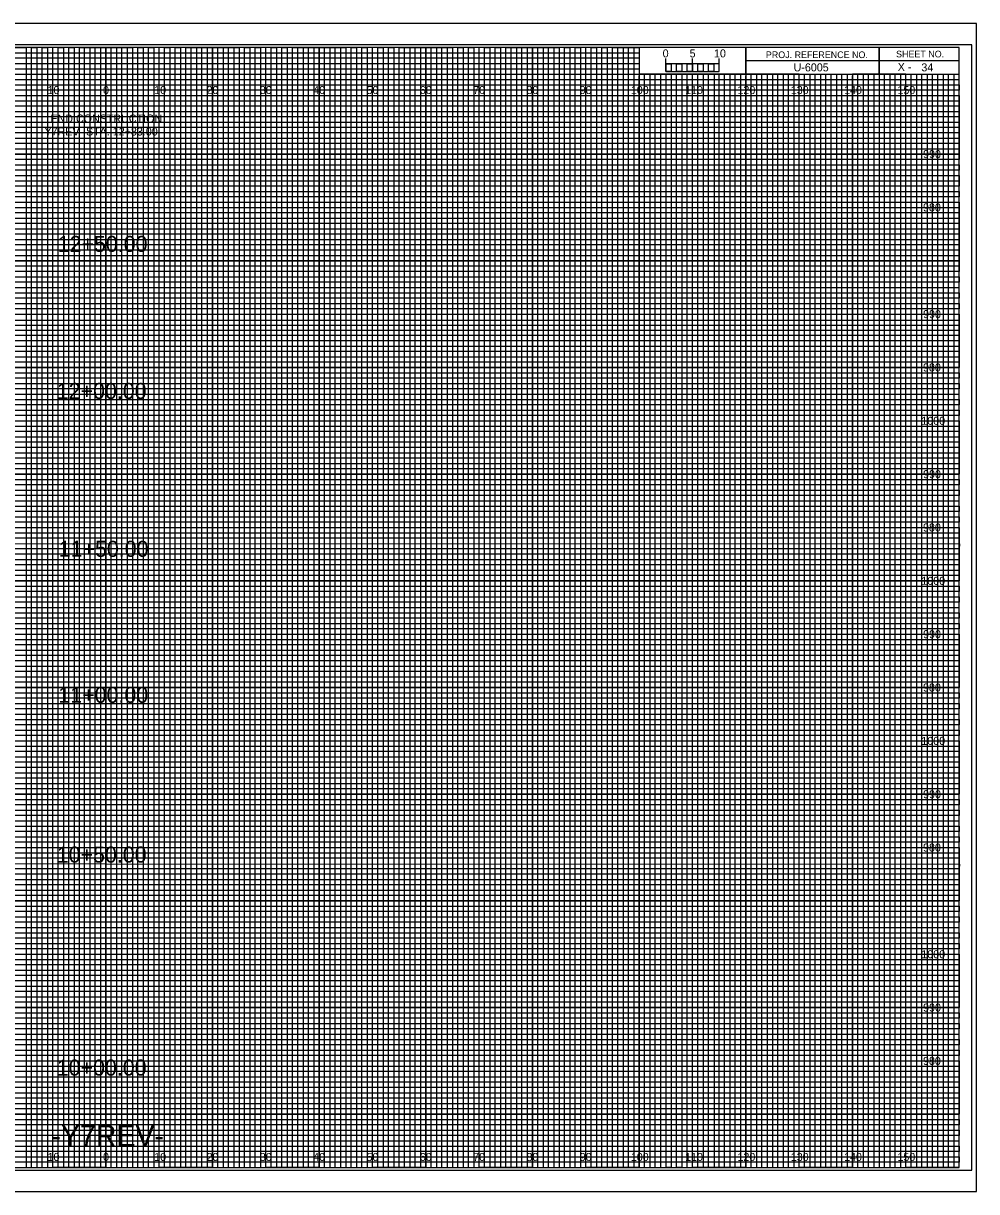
# Model space of a CAD drawing. Extents: x -13 to 323, y -5 to 215.
# Drawn here: x 144.5 to 323.3, y -4.5 to 214.5 of the extents above; entities that cross this region are included whole.
import ezdxf

# ---------------------------------------------------------------- set-up
doc = ezdxf.new("R2010")
doc.units = 0
for name, color, linetype in [('Prop XS Alignment Label', 7, 'Continuous'), ('Prop XS Bar Scale Labels', 7, 'Continuous'), ('Prop XS Elevation Labels', 7, 'Continuous'), ('Prop XS Label Text', 7, 'Continuous'), ('Prop XS Offset Labels', 7, 'Continuous'), ('Prop XS Project Number', 7, 'Continuous'), ('Prop XS Sheet Number', 7, 'Continuous'), ('Prop XS Station Labels', 7, 'Continuous'), ('Sheet Cross Section CELL', 7, 'Continuous'), ('Sheet Cross Section Grid Major CELL', 7, 'Continuous'), ('Sheet Cross Section Grid Middle CELL', 7, 'Continuous'), ('Sheet Cross Section Grid Minor 1 CELL', 7, 'Continuous'), ('Sheet Cross Section Grid Minor 2 CELL', 7, 'Continuous'), ('Sheet Cross Section Scale CELL', 7, 'Continuous'), ('Sheet Cutting Line CELL', 7, 'Continuous'), ('Sheet DOT Grid CELL', 7, 'Continuous'), ('Sheet Plot Border Inside CELL', 7, 'Continuous'), ('Sheet Plot Border Outside CELL', 7, 'Continuous')]:
    doc.layers.add(name, color=color, linetype=linetype)

msp = doc.modelspace()

# ---------------------------------------------------------------- linework, layer by layer
at = {"layer": 'Sheet Cross Section CELL'}
for p, q in [((305, 210), (305, 205)), ((305, 205), (305, 210)), ((280, 207.5), (280, 205)), ((320, 207.49), (280, 207.49)), ((280, 205), (320, 205))]:
    msp.add_line(p, q, dxfattribs=at)
for points in [[(320, 210), (0, 210), (0, 0), (320, 0)], [(280, 210), (260, 210), (260, 205.03), (280, 205.03)], [(320, 210), (280, 210), (280, 205), (320, 205)]]:
    msp.add_lwpolyline(points, close=True, dxfattribs=at)
at = {"layer": 'Sheet Cross Section Grid Major CELL'}
for p, q in [((150, 210), (140, 210)), ((150, 0), (150, 210)), ((170, 210), (160, 210)), ((160, 210), (160, 0)), ((170, 0), (170, 210)), ((190, 210), (180, 210)), ((180, 210), (180, 0)), ((190, 0), (190, 210)), ((210, 210), (200, 210)), ((200, 210), (200, 0)), ((210, 0), (210, 210)), ((230, 210), (220, 210)), ((220, 210), (220, 0)), ((230, 0), (230, 210)), ((250, 210), (240, 210)), ((240, 210), (240, 0)), ((250, 0), (250, 210)), ((260, 210), (260, 0)), ((270, 0), (270, 205)), ((290, 205), (280, 205)), ((280, 205), (280, 0)), ((290, 0), (290, 205)), ((310, 205), (300, 205)), ((300, 205), (300, 0)), ((310, 0), (310, 205)), ((160, 0), (150, 0)), ((180, 0), (170, 0)), ((200, 0), (190, 0)), ((220, 0), (210, 0)), ((240, 0), (230, 0)), ((260, 0), (250, 0)), ((280, 0), (270, 0)), ((300, 0), (290, 0)), ((320, 0), (310, 0)), ((320, 0), (320, 0))]:
    msp.add_line(p, q, dxfattribs=at)
for points in [[(0, 200), (320, 200), (320, 190), (0, 190)], [(0, 180), (320, 180), (320, 170), (0, 170)], [(0, 160), (320, 160), (320, 150), (0, 150)], [(0, 140), (320, 140), (320, 130), (0, 130)], [(0, 120), (320, 120), (320, 110), (0, 110)], [(0, 100), (320, 100), (320, 90), (0, 90)], [(0, 80), (320, 80), (320, 70), (0, 70)], [(0, 60), (320, 60), (320, 50), (0, 50)], [(0, 40), (320, 40), (320, 30), (0, 30)], [(0, 20), (320, 20), (320, 10), (0, 10)]]:
    msp.add_lwpolyline(points, dxfattribs=at)
at = {"layer": 'Sheet Cross Section Grid Middle CELL'}
for points in [[(135, 210), (145, 210), (145, 0), (155, 0), (155, 210), (165, 210), (165, 0), (175, 0), (175, 210), (185, 210), (185, 0), (195, 0), (195, 210), (205, 210), (205, 0), (215, 0), (215, 210), (225, 210), (225, 0), (235, 0), (235, 210), (245, 210), (245, 0), (255, 0), (255, 210), (259.93, 210), (260, 210), (260, 205), (264.99, 205), (264.99, 0), (275, 0), (275, 205), (285, 205), (285, 0), (295, 0), (295, 205), (305, 205), (305, 0), (315, 0), (315, 205)], [(0, 205), (275, 205)], [(0, 185), (320, 185), (320, 195), (0, 195)], [(0, 165), (320, 165), (320, 175), (0, 175)], [(0, 145), (320, 145), (320, 155), (0, 155)], [(0, 125), (320, 125), (320, 135), (0, 135)], [(0, 105), (320, 105), (320, 115), (0, 115)], [(0, 85), (320, 85), (320, 95), (0, 95)], [(0, 65), (320, 65), (320, 75), (0, 75)], [(0, 45), (320, 45), (320, 55), (0, 55)], [(0, 25), (320, 25), (320, 35), (0, 35)], [(0, 5), (320, 5), (320, 15), (0, 15)]]:
    msp.add_lwpolyline(points, dxfattribs=at)
at = {"layer": 'Sheet Cross Section Grid Minor 1 CELL'}
for p, q in [((0, 209), (260, 209)), ((260, 209), (260, 207.98)), ((260, 207.98), (0, 207.98)), ((0, 207), (260, 207)), ((260, 205.89), (0, 205.89)), ((260, 207), (260, 205.89)), ((0, 204), (320, 204))]:
    msp.add_line(p, q, dxfattribs=at)
for points in [[(0, 203), (270, 203), (320, 203), (320, 202), (0, 202)], [(0, 201), (320, 201), (320, 199), (0, 199)], [(0, 198), (320, 198), (320, 197), (0, 196.98)], [(0, 196), (320, 196), (320, 194), (0, 194)], [(0, 193), (320, 193), (320, 192), (0, 192)], [(0, 191), (320, 191), (320, 189), (0, 189)], [(0, 188), (320, 188), (320, 187), (0, 187)], [(0, 186), (320, 186), (320, 184), (0, 184)], [(0, 183), (320, 183), (320, 182), (0, 182)], [(0, 181), (320, 181), (320, 179), (0, 179)], [(0, 178), (320, 178), (320, 177), (0, 177)], [(0, 176), (320, 176), (320, 173.95), (320, 173), (320, 172), (0, 172)], [(0, 174), (320, 174), (320, 173), (0, 173)], [(0, 171), (320, 171), (320, 169), (0, 169.03)], [(0, 169.03), (320, 169), (320, 168), (0, 168)], [(0, 167), (320, 167), (320, 166), (0, 166)], [(0, 164), (320, 164), (320, 163), (0, 163)], [(0, 162), (320, 162), (320, 161), (0, 161)], [(-0.07, 158.89), (320, 158.89), (320, 157.88), (-0.07, 157.88)], [(0, 157), (320, 157), (320, 156), (0, 156)], [(0, 154), (320, 154), (320, 153), (0, 153)], [(0, 152), (320, 152), (320, 151), (0, 151)], [(0, 149), (320, 149), (320, 148), (0, 148)], [(0, 147), (320, 147), (320, 146), (0, 146)], [(0, 144), (320, 144), (320, 143), (0, 143)], [(0, 142), (320, 142), (320, 141), (0, 141)], [(0, 139), (320, 139), (319.99, 137.98), (0, 138)], [(0, 137), (320, 137), (320, 136), (0, 136)], [(0, 134), (320, 134), (320, 133), (0, 133)], [(0, 132), (320, 132), (320, 131), (0, 131)], [(0, 129), (320, 129), (320, 128), (0, 128)], [(0, 127), (320, 127), (320, 126), (0, 126)], [(0, 124), (320, 124), (320, 123), (0, 123)], [(0, 122), (320, 122), (320, 121), (0, 121)], [(0, 119), (320, 119), (320, 118), (0, 118)], [(0, 116.99), (320.07, 116.91), (320, 116), (0, 116)], [(0, 114), (320, 114), (320, 113), (0, 113)], [(0, 112), (320, 112), (320, 111), (0, 111)], [(0, 109), (320, 109), (320, 108), (0, 108)], [(0, 107), (320, 107), (320, 106), (0, 106)], [(0, 104), (320, 104), (320, 103), (0, 103)], [(0, 102), (320, 102), (320, 101), (0, 101)], [(0, 99), (320, 99), (320, 98), (0, 98)], [(0, 97), (320, 97), (320, 96), (0, 96)], [(0, 94), (320, 94), (320, 93), (0, 93)], [(0, 92), (320, 92), (320, 91), (0, 91)], [(0, 89), (320, 89), (320, 88), (0, 88)], [(0, 87), (320, 87), (320, 86), (0, 86)], [(0, 84), (320, 84), (320, 83), (0, 83)], [(0, 82), (320, 82), (320, 81), (0, 81)], [(0, 79), (320, 79), (319.99, 77.98), (0, 78)], [(0, 77), (320, 77), (320, 76), (0, 76)], [(0, 74), (320, 74), (320, 73), (0, 73)], [(0, 72), (320, 72), (320, 71), (0, 71)], [(0, 69), (320, 69), (320, 68), (0, 68)], [(0, 67), (320, 67), (320, 66), (0, 66)], [(0, 64), (320, 64), (320, 63), (0, 63)], [(0, 62), (320, 62), (320, 61), (0, 61)], [(0, 59), (320, 59), (320, 58), (0, 58)], [(0, 56.99), (320.07, 56.91), (320, 56), (0, 56)], [(0, 54), (320, 54), (320, 53), (0, 53)], [(0, 52), (320, 52), (320, 51), (0, 51)], [(0, 49), (320, 49), (320, 48), (0, 48)], [(0, 47), (320, 47), (320, 46), (0, 46)], [(0, 44), (320, 44), (320, 43), (0, 43)], [(0, 42), (320, 42), (320, 41), (0, 41)], [(0, 39), (320, 39), (320, 38), (0, 38)], [(0, 37), (320, 37), (320, 36), (0, 36)], [(0, 34), (320, 34), (320, 33), (0, 33)], [(0, 32), (320, 32), (320, 31), (0, 31)], [(0, 29), (320, 29), (320, 28), (0, 28)], [(0, 27), (320, 27), (320, 26), (0, 26)], [(0, 24), (320, 24), (320, 23), (0, 23)], [(0, 22), (320, 22), (320, 21), (0, 21)], [(0, 19), (320, 19), (320, 18), (0, 18)], [(0, 17), (320, 17), (320, 16), (0, 16)], [(0, 14), (320, 14), (320, 13), (0, 13)], [(0, 12), (320, 12), (320, 11), (0, 11)], [(0, 9), (320, 9), (320, 8), (0, 8)], [(0, 7), (320, 7), (320, 6), (0, 6)], [(0, 4), (320, 4), (320, 3), (0, 3)], [(0, 2), (320, 2), (320, 1), (0, 1)]]:
    msp.add_lwpolyline(points, dxfattribs=at)
at = {"layer": 'Sheet Cross Section Grid Minor 2 CELL'}
for p, q in [((267, 205), (266.01, 205)), ((266.01, 205), (266.01, 0)), ((267, 0), (267, 205)), ((269, 205), (268, 205)), ((268, 205), (268, 0)), ((269, 0), (269, 205)), ((266.01, 0), (265, 0)), ((268, 0), (267, 0))]:
    msp.add_line(p, q, dxfattribs=at)
for points in [[(145, 0), (146, 0), (146, 210), (147, 210), (147, 0)], [(147, 0), (148, 0), (148, 210), (149, 210), (149, 0)], [(150, 0), (151, 0), (151, 210), (152, 210), (152, 0)], [(152, 0), (153, 0), (153, 210), (154, 210), (154, 0)], [(155, 0), (156, 0), (156, 210), (157, 210), (157, 0)], [(157, 0), (158, 0), (158, 210), (159, 210), (159, 0)], [(160, 0), (161, 0), (161, 210), (162, 210), (162, 0)], [(162, 0), (163, 0), (163, 210), (164, 210), (164, 0)], [(165, 0), (166, 0), (166, 210), (167, 210), (167, 0)], [(167, 0), (168, 0), (168, 210), (169, 210), (169, 0)], [(170, 0), (171, 0), (171, 210), (172, 210), (172, 0)], [(172, 0), (173, 0), (173, 210), (174, 210), (174, 0)], [(175, 0), (176, 0), (176, 210), (177, 210), (177, 0)], [(177, 0), (178, 0), (178, 210), (179, 210), (179, 0)], [(180, 0), (181, 0), (181, 210), (182, 210), (182, 0)], [(182, 0), (183, 0), (183, 210), (184, 210), (184, 0)], [(185, 0), (186, 0), (186, 210), (187, 210), (187, 0)], [(187, 0), (188, 0), (188, 210), (189, 210), (189, 0)], [(190, 0), (191, 0), (191, 210), (192, 210), (192, 0)], [(192, 0), (193, 0), (193, 210), (194, 210), (194, 0)], [(195, 0), (196, 0), (196, 210), (197, 210), (197, 0)], [(197, 0), (198, 0), (198, 210), (199, 210), (199, 0)], [(200, 0), (201, 0), (201, 210), (202, 210), (202, 0)], [(202, 0), (203, 0), (203, 210), (204, 210), (204, 0)], [(205, 0), (206, 0), (206, 210), (207, 210), (207, 0)], [(207, 0), (208, 0), (208, 210), (209, 210), (209, 0)], [(210, 0), (211, 0), (211, 210), (212, 210), (212, 0)], [(212, 0), (213, 0), (213, 210), (214, 210), (214, 0)], [(215, 0), (216, 0), (216, 210), (217, 210), (217, 0)], [(217, 0), (218, 0), (218, 210), (219, 210), (219, 0)], [(220, 0), (221, 0), (221, 210), (222, 210), (222, 0)], [(222, 0), (223, 0), (223, 210), (224, 210), (224, 0)], [(225, 0), (226, 0), (226, 210), (227, 210), (227, 0)], [(227, 0), (228, 0), (228, 210), (229, 210), (229, 0)], [(230, 0), (231, 0), (231, 210), (232, 210), (232, 0)], [(232, 0), (233, 0), (233, 210), (234, 210), (234, 0)], [(235, 0), (236, 0), (236, 210), (237, 210), (237, 0)], [(237, 0), (238, 0), (238, 210), (239, 210), (239, 0)], [(240, 0), (241, 0), (241, 210), (242, 210), (242, 0)], [(242, 0), (243, 0), (243, 210), (244, 210), (244, 0)], [(245, 0), (246, 0), (246, 210), (247, 210), (247, 0)], [(247, 0), (248, 0), (248, 210), (249, 210), (249, 0)], [(250, 0), (251, 0), (251, 210), (252, 210), (252, 0)], [(252, 0), (253, 0), (253, 210), (254, 210), (254, 0)], [(255, 0), (256, 0), (256, 210), (257, 210), (257, 0)], [(257, 0), (258, 0), (258, 210), (259, 210), (259, 0)], [(260, 0), (261, 0), (261, 205), (262.02, 205), (262.02, 0)], [(262, 0), (263, 0), (263, 205), (263.99, 205), (263.99, 0)], [(270, 0), (270.98, 0), (270.98, 205), (272, 205), (272, 0)], [(272, 0), (273, 0), (273, 205), (274.05, 205), (274.05, 0)], [(275, 0), (276, 0), (276, 205), (277, 205), (277, 0)], [(277, 0), (278, 0), (278, 205), (279, 205), (279, 0)], [(280, 0), (281, 0), (281, 205), (282, 205), (282, 0)], [(282, 0), (283, 0), (283, 205), (284, 205), (284, 0)], [(285, 0), (286, 0), (286, 205), (287, 205), (287, 0)], [(287, 0), (288, 0), (288, 205), (289, 205), (289, 0)], [(290, 0), (291, 0), (291, 205), (292, 205), (292, 0)], [(292, 0), (293, 0), (293, 205), (294, 205), (294, 0)], [(295, 0), (296, 0), (296, 205), (297, 205), (297, 0)], [(297, 0), (298, 0), (298, 205), (299, 205), (299, 0)], [(300, 0), (301, 0), (301, 205), (302, 205), (302, 0)], [(302, 0), (303, 0), (303, 205), (304, 205), (304, 0)], [(305, 0), (306, 0), (306, 205), (307, 205), (307, 0)], [(307, 0), (308, 0), (308, 205), (309, 205), (309, 0)], [(310, 0), (311, 0), (311, 205), (312, 205), (312, 0)], [(312, 0), (313, 0), (313, 205), (314, 205), (314, 0)], [(315, 0), (316, 0), (316, 205), (317, 205), (317, 0)], [(317, 0), (318, 0), (318, 205), (319, 205), (319, 0)]]:
    msp.add_lwpolyline(points, dxfattribs=at)
at = {"layer": 'Sheet Cross Section Scale CELL'}
for p, q in [((265, 205.49), (265, 207.9)), ((265, 206.9), (265, 207.9)), ((270, 205.49), (270, 207.9)), ((275, 205.49), (275, 207.9)), ((275, 206.9), (275, 207.9))]:
    msp.add_line(p, q, dxfattribs=at)
for points in [[(275, 206.9), (265, 206.9), (265, 205.49), (275, 205.49)], [(265, 206.9), (266, 206.9), (266, 205.49), (265, 205.49)], [(267, 206.9), (268, 206.9), (268, 205.49), (267, 205.49)], [(269, 206.9), (270, 206.9), (270, 205.49), (269, 205.49)], [(271, 206.9), (272, 206.9), (272, 205.49), (271, 205.49)], [(273, 206.9), (274, 206.9), (274, 205.49), (273, 205.49)]]:
    msp.add_lwpolyline(points, close=True, dxfattribs=at)
at = {"layer": 'Sheet Cutting Line CELL'}
for p, q in [((323.3, 214.5), (-13.4, 214.5)), ((-13.4, -4.5), (323.3, -4.5))]:
    msp.add_line(p, q, dxfattribs=at)
at = {"layer": 'Sheet DOT Grid CELL'}
for p, q in [((150, 0), (150, 210)), ((160, 0), (160, 210)), ((170, 0), (170, 210)), ((180, 0), (180, 210)), ((190, 0), (190, 210)), ((200, 0), (200, 210)), ((210, 0), (210, 210)), ((220, 0), (220, 210)), ((230, 0), (230, 210)), ((240, 0), (240, 210)), ((250, 0), (250, 210)), ((260, 0), (260, 204.69)), ((270, 0), (270, 204.69)), ((280, 0), (280, 204.69)), ((290, 0), (290, 204.69)), ((300, 0), (300, 204.69)), ((310, 0), (310, 204.69)), ((0, 200), (320, 200)), ((0, 190), (320, 190)), ((0, 180), (320, 180)), ((0, 170), (320, 170)), ((0, 160), (320, 160)), ((0, 150), (320, 150)), ((0, 140), (320, 140)), ((0, 130), (320, 130)), ((0, 120), (320, 120)), ((0, 110), (320, 110)), ((0, 100), (320, 100)), ((0, 90), (320, 90)), ((0, 80), (320, 80)), ((0, 70), (320, 70)), ((0, 60), (320, 60)), ((0, 50), (320, 50)), ((0, 40), (320, 40)), ((0, 30), (320, 30)), ((0, 20), (320, 20)), ((0, 10), (320, 10))]:
    msp.add_line(p, q, dxfattribs=at)
at = {"layer": 'Sheet Plot Border Inside CELL'}
msp.add_lwpolyline([(-10.8, -0.5), (322.4, -0.5), (322.4, 210.5), (-10.8, 210.5)], close=True, dxfattribs=at)
at = {"layer": 'Sheet Plot Border Outside CELL'}
msp.add_lwpolyline([(-13.4, -4.5), (323.3, -4.5), (323.3, 214.5), (-13.4, 214.5)], close=True, dxfattribs=at)

# ---------------------------------------------------------------- texts
at = {"layer": 'Prop XS Alignment Label'}
msp.add_text('-Y7REV-', height=4, dxfattribs=at).set_placement((149.77, 4))
at = {"layer": 'Prop XS Bar Scale Labels'}
for s, p in [('5', (269.47, 208.12)), ('10', (274.04, 208.12))]:
    msp.add_text(s, height=1.5, dxfattribs=at).set_placement(p)
at = {"layer": 'Prop XS Elevation Labels'}
for s, p in [('990', (313.26, 189.25)), ('980', (313.24, 179.25)), ('990', (313.26, 159.25)), ('980', (313.24, 149.25)), ('1000', (312.92, 139.25)), ('990', (313.26, 129.25)), ('980', (313.24, 119.25)), ('1000', (312.92, 109.25)), ('990', (313.26, 99.25)), ('980', (313.24, 89.25)), ('1000', (312.92, 79.25)), ('990', (313.26, 69.25)), ('980', (313.24, 59.25)), ('1000', (312.92, 39.25)), ('990', (313.26, 29.25)), ('980', (313.24, 19.25))]:
    msp.add_text(s, height=1.5, dxfattribs=at).set_placement(p)
at = {"layer": 'Prop XS Label Text'}
for s, p in [('END CONSTRUCTION', (149.58, 195.91)), ('-Y7REV- STA. 12+83.00', (147.79, 193.48))]:
    msp.add_text(s, height=1.5, dxfattribs=at).set_placement(p)
at = {"layer": 'Prop XS Offset Labels'}
for s, p in [('10', (149.04, 201.25)), ('0', (159.45, 201.25)), ('0', (159.45, 201.25)), ('10', (169.04, 201.25)), ('20', (178.86, 201.25)), ('30', (188.86, 201.25)), ('40', (198.86, 201.25)), ('50', (208.86, 201.25)), ('60', (218.86, 201.25)), ('70', (228.86, 201.25)), ('80', (238.86, 201.25)), ('90', (248.86, 201.25)), ('100', (258.44, 201.25)), ('110', (268.62, 201.25)), ('120', (278.44, 201.25)), ('130', (288.44, 201.25)), ('140', (298.44, 201.25)), ('150', (308.44, 201.25)), ('10', (149.04, 1.25)), ('0', (159.45, 1.25)), ('0', (159.45, 1.25)), ('10', (169.04, 1.25)), ('20', (178.86, 1.25)), ('30', (188.86, 1.25)), ('40', (198.86, 1.25)), ('50', (208.86, 1.25)), ('60', (218.86, 1.25)), ('70', (228.86, 1.25)), ('80', (238.86, 1.25)), ('90', (248.86, 1.25)), ('100', (258.44, 1.25)), ('110', (268.62, 1.25)), ('120', (278.44, 1.25)), ('130', (288.44, 1.25)), ('140', (298.44, 1.25)), ('150', (308.44, 1.25))]:
    msp.add_text(s, height=1.5, dxfattribs=at).set_placement(p)
at = {"layer": 'Prop XS Project Number'}
msp.add_text('U-6005', height=1.5, dxfattribs=at).set_placement((288.97, 205.5))
at = {"layer": 'Prop XS Sheet Number'}
msp.add_text('34', height=1.5, dxfattribs=at).set_placement((312.93, 205.5))
at = {"layer": 'Prop XS Station Labels'}
for s, p in [('12+50.00', (150.94, 171.66)), ('12+00.00', (150.77, 144.09)), ('11+50.00', (151.13, 114.5)), ('11+00.00', (151.07, 87.13)), ('10+50.00', (150.77, 57.18)), ('10+00.00', (150.77, 17.25))]:
    msp.add_text(s, height=3, dxfattribs=at).set_placement(p)
at = {"layer": 'Sheet Cross Section CELL'}
for s, height, p in [('PROJ. REFERENCE NO.', 1.25, (283.77, 207.99)), ('SHEET NO.', 1.25, (308.19, 208.12)), ('X -    ', 1.5, (308.5, 205.58))]:
    msp.add_text(s, height=height, dxfattribs=at).set_placement(p)
at = {"layer": 'Sheet Cross Section Scale CELL'}
msp.add_text('0', height=1.5, dxfattribs=at).set_placement((264.41, 208.12))

doc.saveas('drawing.dxf')
